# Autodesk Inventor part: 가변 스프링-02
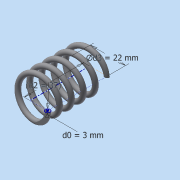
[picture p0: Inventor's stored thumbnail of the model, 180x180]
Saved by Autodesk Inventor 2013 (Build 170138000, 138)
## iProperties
Created: 2014-12
Part Number: 가변 스프링-02
Material: 강철, 탄소
Document SubType Name: Modeling
Designer: WINDOWS7
Density: 7.87 g/cm^3
Mass: 18.7435 g
Surface Area: 32.4002 cm^2
Volume: 2.38164 cm^3
Author: WINDOWS7
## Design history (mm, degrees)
sketch "스케치1"
  geometry: L1 (0, 0)-(11, 0); L2 (11, 0)-(11, 25.358); L3 (11, 25.358)-(0, 25.358); L4 (0, 25.358)-(0, 0); C1 r 1.5 at (11, 0)
  constraints: 8 end point, 2 parallel, 1 centre point, 1 coincident, 1 horizontal, 1 perpendicular
  dimensions: "d0" = 3 diameter of C1; "d2" = 25.35829 distance of L3.end L1.start (derived); "d3" = 22 diameter of L2 L4
feature "코일1" pitch "d4" = 10; turns "d6" = 5; dims "d5" = 25.35829 (= d2), "d7" = 0, angle "d8" = 90 deg, angle "d9" = 90 deg, "d10" = 0, "d11" = 0
node "작업 평면1"
sketch "스케치2"
  geometry: L1 (-12.5, 0)-(-9.5, 0) reference; 1 further point
  constraints: 1 horizontal alignment
extrude "돌출1" cut sketch "스케치2" distance "d13" = 10; taper "d14" = 0 deg
node "작업 평면2"
sketch "스케치3"
  geometry: L1 (-9.5, 0)-(-12.5, 0) reference; 1 further point
  constraints: 1 horizontal alignment
extrude "돌출2" cut sketch "스케치3" distance "d16" = 10; taper "d17" = 0 deg
node "솔리드1"
node "절단 모서리 투영1"
node "절단 모서리 투영2"
other parameters: "d12" = 0, "d15" = 25.35829 (= d2)
